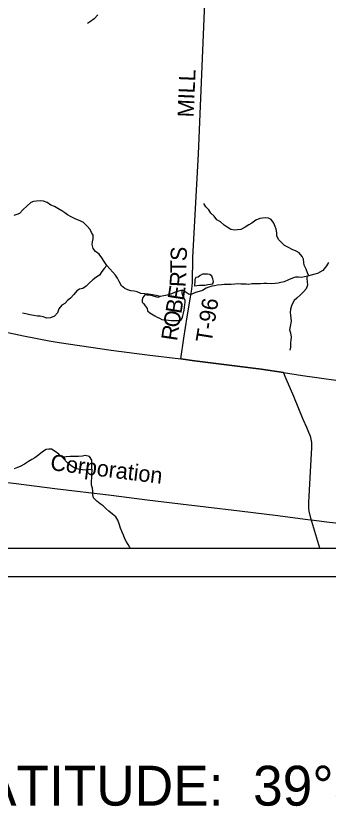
# Model space of a CAD drawing. Extents: x 0 to 36.5, y 0 to 25.3.
# Drawn here: x 3.297 to 4.396, y 13.194 to 15.97 of the extents above; entities that cross this region are included whole.
import ezdxf

# ---------------------------------------------------------------- set-up
doc = ezdxf.new("R2010")
doc.units = 0
for name, color, linetype in [('DV_X_Township_Line', 7, 'Continuous'), ('GM_X_County_Road', 7, 'Continuous'), ('GM_X_Minor_Lake', 7, 'Continuous'), ('GM_X_Minor_River', 7, 'Continuous'), ('GM_X_Rail_Line', 7, 'Continuous'), ('GM_X_Rail_Line_Text', 7, 'Continuous'), ('GM_X_Township_Road', 7, 'Continuous'), ('GM_X_Township_Road_Text', 7, 'Continuous'), ('SH_Cut_Line', 7, 'Continuous'), ('SH_Data', 7, 'Continuous'), ('SH_Text', 7, 'Continuous')]:
    doc.layers.add(name, color=color, linetype=linetype)

msp = doc.modelspace()

# ---------------------------------------------------------------- linework, layer by layer
at = {"layer": 'DV_X_Township_Line'}
msp.add_lwpolyline([(2.1, 16.2788), (2.1, 14.1), (8.9, 14.1), (8.9, 14.8674), (8.5228, 15.0526), (8.0723, 15.2737), (7.8139, 15.4027), (7.7814, 15.4189), (7.7552, 15.432), (7.703, 15.458), (6.8419, 15.8878), (6.6079, 15.9978), (5.1383, 16.6527), (4.8891, 16.7511), (4.0938, 16.595), (2.4938, 16.3413), (2.1039, 16.2931)], close=True, dxfattribs=at)
at = {"layer": 'GM_X_County_Road'}
for points in [[(2.6624, 14.9924), (2.8607, 14.9479), (2.9859, 14.9201), (3.0216, 14.9117), (3.093, 14.8968), (3.2535, 14.8609), (3.3251, 14.8458), (3.4146, 14.8282), (3.4505, 14.8223), (3.6326, 14.7957), (3.7599, 14.7792), (3.8775, 14.7645)], [(3.8775, 14.7645), (3.9261, 14.758), (3.9917, 14.7501), (4.1604, 14.7282), (4.2393, 14.7169)], [(4.2393, 14.7169), (4.3059, 14.707), (4.4899, 14.6813), (4.9211, 14.6198), (5.227, 14.5775), (5.3061, 14.5659), (5.3593, 14.5586), (5.3831, 14.556), (5.5195, 14.5361), (6.104, 14.453), (6.2799, 14.4286), (6.3234, 14.4219), (6.333, 14.4203), (6.3453, 14.4176)]]:
    msp.add_lwpolyline(points, dxfattribs=at)
at = {"layer": 'GM_X_Minor_Lake'}
for points in [[(3.9884, 15.0518), (3.9871, 15.0555), (3.98, 15.0613), (3.972, 15.0626), (3.9629, 15.0627), (3.9538, 15.0621), (3.9454, 15.0577), (3.9385, 15.0521), (3.9305, 15.0503), (3.9266, 15.0435), (3.9269, 15.0378), (3.9262, 15.0218)], [(3.9262, 15.0218), (3.9441, 15.0235), (3.9532, 15.0238), (3.9634, 15.0243), (3.9733, 15.0257), (3.9817, 15.0275), (3.9905, 15.0289), (3.9932, 15.0368), (3.9907, 15.0456), (3.9884, 15.0518)], [(3.8047, 14.9836), (3.7973, 14.9807), (3.7897, 14.9823), (3.7814, 14.9855), (3.7739, 14.9875), (3.7663, 14.9884), (3.7587, 14.9889), (3.7511, 14.9901), (3.7445, 14.9808), (3.7425, 14.9721), (3.7416, 14.9637), (3.748, 14.9587), (3.7524, 14.9506), (3.7598, 14.9418), (3.7601, 14.9334), (3.7687, 14.9261), (3.786, 14.9159), (3.795, 14.9116), (3.8025, 14.9077), (3.8108, 14.9026), (3.8184, 14.9021), (3.8267, 14.9016), (3.8347, 14.9011), (3.8438, 14.9002), (3.8699, 14.8998), (3.8776, 14.9012), (3.8822, 14.908), (3.8854, 14.9166), (3.8867, 14.9253), (3.8891, 14.9359), (3.8908, 14.9462), (3.8917, 14.9553), (3.893, 14.9632), (3.8935, 14.9712), (3.8887, 14.9792), (3.8854, 14.9872), (3.8822, 14.996), (3.8823, 15.0061)], [(3.8823, 15.0061), (3.8698, 15.0024), (3.8557, 14.9984), (3.8427, 14.992), (3.8294, 14.9887), (3.818, 14.9858), (3.8047, 14.9836)]]:
    msp.add_lwpolyline(points, dxfattribs=at)
at = {"layer": 'GM_X_Minor_River'}
for points in [[(3.5862, 15.9732), (3.5728, 15.9585), (3.5602, 15.9495), (3.5492, 15.9431)], [(4.3589, 15.0644), (4.3491, 15.0618), (4.3358, 15.0593), (4.3233, 15.0556), (4.3126, 15.053), (4.3024, 15.0512), (4.2921, 15.0521), (4.2811, 15.0522), (4.2701, 15.0481), (4.256, 15.0425), (4.2415, 15.0358), (4.2297, 15.0325), (4.2202, 15.031), (4.2092, 15.03), (4.1952, 15.0282), (4.1804, 15.0298), (4.1698, 15.0296), (4.158, 15.0289), (4.1477, 15.0282), (4.1375, 15.0283), (4.128, 15.028), (4.117, 15.0262), (4.1075, 15.027), (4.098, 15.0267), (4.0886, 15.0276), (4.0787, 15.0284), (4.0673, 15.0274), (4.0548, 15.026), (4.0426, 15.0261), (4.0305, 15.0258), (4.0206, 15.0251), (4.0066, 15.0233), (3.9959, 15.0215), (3.9864, 15.0197), (3.9765, 15.0171), (3.9666, 15.0127), (3.954, 15.0055), (3.9419, 15.0018), (3.9289, 14.9974), (3.9171, 14.9922), (3.9076, 14.9911), (3.8937, 15.0004), (3.8823, 15.0061), (3.8698, 15.0024), (3.8557, 14.9984), (3.8427, 14.992), (3.8294, 14.9887), (3.818, 14.9858), (3.8047, 14.9836), (3.7915, 14.9872), (3.7778, 14.9896), (3.7638, 14.9916), (3.7509, 14.9928), (3.7377, 14.9948), (3.7241, 14.9999), (3.7142, 15.0022), (3.7021, 15.0042), (3.6919, 15.007), (3.6805, 15.0116), (3.6696, 15.0216), (3.6606, 15.0361), (3.6551, 15.0487), (3.6479, 15.0586), (3.6393, 15.0697), (3.628, 15.0815), (3.6171, 15.093), (3.6078, 15.1064), (3.6003, 15.1197), (3.5909, 15.1327), (3.5781, 15.1419), (3.5691, 15.153), (3.5666, 15.1663), (3.5674, 15.1758), (3.5694, 15.1868), (3.5699, 15.1989), (3.5643, 15.2092), (3.5587, 15.2188), (3.547, 15.2318), (3.5361, 15.2436), (3.5244, 15.2494), (3.5089, 15.2556), (3.4923, 15.2633), (3.4794, 15.2703), (3.4696, 15.2772), (3.4595, 15.2845), (3.4459, 15.2933), (3.4334, 15.2995), (3.4206, 15.3049), (3.4081, 15.3145), (3.3949, 15.3184), (3.3847, 15.3197), (3.3702, 15.319), (3.36, 15.3176), (3.3505, 15.3143), (3.3367, 15.3015), (3.3233, 15.2891), (3.3107, 15.2759), (3.3011, 15.2714), (3.2909, 15.2684)], [(4.3277, 15.0569), (4.3234, 15.0666), (4.3182, 15.0799), (4.3122, 15.094), (4.3108, 15.1035), (4.3094, 15.1149), (4.3049, 15.1248), (4.2937, 15.1375), (4.2838, 15.1432), (4.2698, 15.1487), (4.2566, 15.1564), (4.2419, 15.1633), (4.2306, 15.1744), (4.2216, 15.1844), (4.2156, 15.1973), (4.215, 15.2076), (4.2132, 15.2201), (4.2102, 15.2296), (4.2046, 15.2415), (4.1957, 15.2548), (4.1858, 15.2591), (4.1764, 15.2599), (4.165, 15.2596), (4.1555, 15.2582), (4.1418, 15.2515), (4.1272, 15.2413), (4.1173, 15.2357), (4.104, 15.2271), (4.0891, 15.2196), (4.0773, 15.2175), (4.0671, 15.2164), (4.0542, 15.2192), (4.0406, 15.2276), (4.0304, 15.2342), (4.0173, 15.2464), (4.0044, 15.2526), (3.9954, 15.2664), (3.9838, 15.2771), (3.9767, 15.2885), (3.9657, 15.2985), (3.959, 15.3103)], [(4.3971, 15.1032), (4.3901, 15.0922), (4.3769, 15.0754), (4.3589, 15.0644)], [(3.6171, 15.093), (3.6079, 15.0828), (3.6006, 15.0719), (3.5914, 15.0594), (3.5784, 15.0508), (3.5681, 15.0425), (3.557, 15.0324), (3.5455, 15.0207), (3.5333, 15.0125), (3.5219, 15.0099), (3.5124, 15.0035), (3.502, 14.9911), (3.4901, 14.9783), (3.4794, 14.9696), (3.4703, 14.9598), (3.4599, 14.9535), (3.4488, 14.9403), (3.4438, 14.927), (3.4338, 14.915), (3.4201, 14.909), (3.4068, 14.908), (3.3932, 14.9127), (3.3837, 14.9143), (3.3742, 14.9147), (3.3606, 14.9175), (3.347, 14.9195), (3.3333, 14.9234), (3.3212, 14.925)], [(4.3215, 15.0552), (4.3209, 15.0473), (4.3227, 15.0351), (4.3234, 15.0237), (4.3191, 15.0105), (4.3091, 15.0007), (4.2988, 14.9894), (4.2862, 14.9781), (4.2766, 14.9694), (4.2681, 14.9547), (4.2638, 14.9392), (4.2626, 14.9282), (4.264, 14.9187), (4.2651, 14.9077), (4.2665, 14.8978), (4.2625, 14.8788), (4.2598, 14.8663), (4.2635, 14.8561), (4.2656, 14.8412), (4.2648, 14.831), (4.2639, 14.8211), (4.263, 14.8056), (4.2618, 14.795)], [(3.5019, 14.4221), (3.4883, 14.4218), (3.4746, 14.4204), (3.4605, 14.4201), (3.4493, 14.4305), (3.4364, 14.4401), (3.4236, 14.4474), (3.4141, 14.4479), (3.4039, 14.4461), (3.3916, 14.4382), (3.3783, 14.4284), (3.3649, 14.4179), (3.3535, 14.4112), (3.3416, 14.4044), (3.3283, 14.3951), (3.3134, 14.3872), (3.3035, 14.3831), (3.2917, 14.3783)], [(3.5658, 14.3737), (3.5561, 14.3765), (3.5428, 14.3743), (3.5322, 14.3748), (3.5182, 14.3775), (3.5076, 14.3799), (3.4952, 14.3865), (3.4816, 14.398), (3.4605, 14.4201)], [(3.7003, 14.1), (3.699, 14.102), (3.6927, 14.1126), (3.6867, 14.1229), (3.6815, 14.1328), (3.6759, 14.1458), (3.6711, 14.1561), (3.6659, 14.1709), (3.6615, 14.185), (3.6563, 14.1987), (3.6495, 14.2098), (3.6378, 14.219), (3.6251, 14.2305), (3.6141, 14.2397), (3.6043, 14.2485), (3.5942, 14.2562), (3.5821, 14.265), (3.5712, 14.2769), (3.5686, 14.2871), (3.568, 14.3008), (3.5669, 14.3107), (3.5636, 14.3217), (3.5634, 14.3346), (3.565, 14.3483), (3.5651, 14.362), (3.566, 14.3718), (3.5646, 14.384), (3.5651, 14.3965), (3.5652, 14.4094), (3.5569, 14.4224), (3.5414, 14.4252), (3.5315, 14.4237), (3.5175, 14.4223), (3.5019, 14.4221)]]:
    msp.add_lwpolyline(points, dxfattribs=at)
at = {"layer": 'GM_X_Rail_Line'}
msp.add_lwpolyline([(2.9959, 14.3635), (3.2993, 14.3271), (3.4345, 14.31), (3.6331, 14.2857), (3.7599, 14.2703), (3.8768, 14.2559), (3.9653, 14.2449), (4.0847, 14.2307), (4.1319, 14.225), (4.2195, 14.2143), (4.28, 14.2068), (4.3249, 14.2011), (4.3358, 14.1998), (4.4011, 14.1918), (4.4931, 14.1806), (4.5963, 14.1681), (4.7925, 14.1443), (4.836, 14.139), (4.9328, 14.1267), (5.0153, 14.1165), (5.1077, 14.1057), (5.1561, 14.1)], dxfattribs=at)
at = {"layer": 'GM_X_Township_Road'}
msp.add_line((3.8775, 14.7645), (3.8889, 14.838), dxfattribs=at)
for points in [[(3.9119, 14.9811), (3.9167, 15.0093), (3.9193, 15.0336), (3.9198, 15.1204), (3.9396, 15.4848), (3.9631, 16.0451)], [(3.8889, 14.838), (3.9004, 14.9126), (3.9119, 14.9811)], [(4.2393, 14.7169), (4.1604, 14.7282), (3.9917, 14.7501), (3.9261, 14.758), (3.8775, 14.7645)], [(4.3671, 14.1), (4.3419, 14.1817), (4.335, 14.2055), (4.3292, 14.2296), (4.328, 14.242), (4.3281, 14.2606), (4.3353, 14.3905), (4.3383, 14.4525), (4.3385, 14.4649), (4.3383, 14.4711), (4.3377, 14.4773), (4.3365, 14.4834), (4.3348, 14.4893), (4.3327, 14.4952), (4.3282, 14.5067), (4.3205, 14.5236), (4.3083, 14.5521), (4.2748, 14.6322), (4.2479, 14.695), (4.2393, 14.7169)]]:
    msp.add_lwpolyline(points, dxfattribs=at)
at = {"layer": 'SH_Cut_Line'}
msp.add_lwpolyline([(4.4591, 20.9), (3.3366, 20.9), (3.2612, 20.6041), (2.8463, 19.037), (2.6265, 18.2595), (2.5271, 17.8912), (2.5226, 17.8751), (2.5165, 17.8524), (2.5144, 17.8445), (2.4192, 17.4891), (2.3437, 17.2326), (2.3403, 17.2198), (2.1039, 16.2931), (2.1, 16.2788), (2.1, 14.1), (8.9, 14.1), (8.9, 20.9), (6.1845, 20.9)], dxfattribs=at)
at = {"layer": 'SH_Data'}
for p, q in [((2.1, 14.1), (8.9, 14.1)), ((2, 14), (9, 14))]:
    msp.add_line(p, q, dxfattribs=at)

# ---------------------------------------------------------------- texts
at = {"layer": 'GM_X_Rail_Line_Text'}
msp.add_text('Corporation', height=0.056629, rotation=352.9546, dxfattribs=at).set_placement((3.417, 14.3745))
at = {"layer": 'GM_X_Township_Road_Text'}
for s, height, rotation, p in [('MILL', 0.05682, 87.5921, (3.9228, 15.6122)), ('S', 0.0568, 87.1718, (3.8977, 15.1071)), ('T', 0.0568, 89.3738, (3.8973, 15.0651)), ('R', 0.0568, 86.8286, (3.8946, 15.0158)), ('E', 0.0568, 80.8619, (3.8872, 14.9674)), ('B', 0.0568, 80.6378, (3.8795, 14.9211)), ('T-96', 0.05682, 80.8846, (3.986, 14.8192)), ('O', 0.0568, 80.655, (3.8714, 14.8718)), ('R', 0.0568, 81.4636, (3.8645, 14.8259))]:
    msp.add_text(s, height=height, rotation=rotation, dxfattribs=at).set_placement(p)
at = {"layer": 'SH_Text'}
msp.add_text('LATITUDE:  39°56\'24"     LONGITUDE:  83°29\'52"', height=0.14, dxfattribs=at).set_placement((3.071, 13.1959))

doc.saveas('drawing.dxf')
